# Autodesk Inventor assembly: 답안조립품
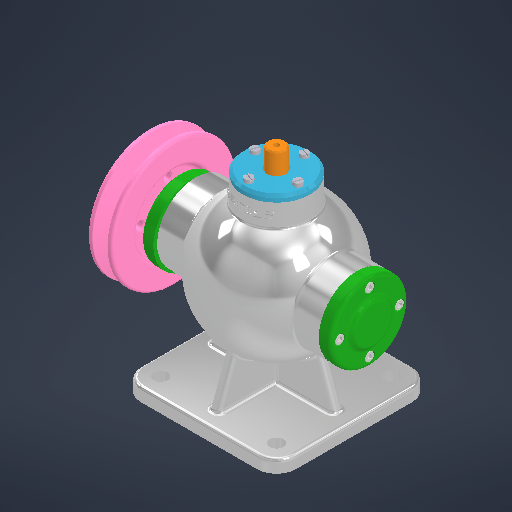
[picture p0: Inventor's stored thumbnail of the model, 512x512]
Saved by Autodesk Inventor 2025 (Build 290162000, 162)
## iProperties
Created: 2025-08
Part Number: 답안조립품
Document SubType Name: Assembly
Designer: infra005
Author: infra005
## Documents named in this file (15)
- C:\Users\infra005\Desktop\750807V1013\답안조립품.iam
- C:\Users\infra005\Desktop\750807V1013\부품29.ipt
- C:\Users\infra005\Desktop\750807V1013\V-벨트풀리\V-벨트풀리.ipt
- C:\Users\infra005\Desktop\750807V1013\너트 M8\너트 M8.ipt
- C:\Users\infra005\Desktop\750807V1013\뒤커버\뒤커버.ipt
- C:\Users\infra005\Desktop\750807V1013\베어링- 6202\베어링- 6202.ipt
- C:\Users\infra005\Desktop\750807V1013\볼트 M4 x 12\볼트 M4 x 12.ipt
- C:\Users\infra005\Desktop\750807V1013\볼트 M4 x 16\볼트 M4 x 16.ipt
- C:\Users\infra005\Desktop\750807V1013\상부커버\상부커버.ipt
- C:\Users\infra005\Desktop\750807V1013\슬라이드\슬라이드.ipt
- C:\Users\infra005\Desktop\750807V1013\앞커버\앞커버.ipt
- C:\Users\infra005\Desktop\750807V1013\오일실 15 30 7\오일실 15 30 7.ipt
- C:\Users\infra005\Desktop\750807V1013\칼라\칼라.ipt
- C:\Users\infra005\Desktop\750807V1013\키 4 x 4 x 12\키 4 x 4 x 12.ipt
- C:\Users\infra005\Desktop\750807V1013\편심축\편심축.ipt
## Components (1 placed, 1 different names)
1. V-벨트풀리:1
